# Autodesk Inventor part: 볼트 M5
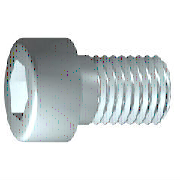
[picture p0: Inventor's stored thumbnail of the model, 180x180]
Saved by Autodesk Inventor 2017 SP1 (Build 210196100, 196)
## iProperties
IsCustomPart: 1
Created: 2012-02
Part Number: 볼트 M5
Material: 강철, 연강
Description: 6각머리 태핑 나사
Document SubType Name: Modeling
Standard: KS B 1003
Designer: mduedu
Standards Organization: KS
Language: ko-KR
Size Designation: M 5 x 16
Categories: <MemberInstance><Categories><Category DisplayName="조임쇠" InternalName="e4da775c-781d-43d5-af7c-5136215cf5a6" Mnemonic="FSTN"><Category DisplayName="볼트" InternalN
Density: 1 g/cm^3
Appearance: 강철
Author: mduedu
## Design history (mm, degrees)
sketch "스케치1"
  geometry: L1 (-1.167, 0)-(16, 0); L2 (16, 0)-(16, 2.5); L3 (16, 2.5)-(2, 2.5); L4 (2, 2.5)-(1.509, 2.5); L5 (1.509, 2.5)-(0, 2.5); L6 (0, 2.5)-(0, 4.25); L7 (0, 4.25)-(-5, 4.25); L8 (-5, 4.25)-(-5, 2.309); L9 (-5, 2.309)-(-2.5, 2.309); L10 (-2.5, 2.309)-(-1.167, 0); L11 (-9.2, 0)-(20.2, 0) reference; L12 (0, -0.85)-(0, 5.1) reference; L13 (2, 2.5)-(0, 2.5)
  constraints: 22 end point, 6 parallel, 2 collinear, 2 perpendicular, 1 horizontal, 1 point on line
  dimensions: "d1" = 14 distance from line of L3.end L2 (= GEL); "d2" = 0.49086 distance of L4.end L3.end (computed from GAL); "d3" = 5 distance between parallel lines of L8 L6 (= KOH); "d4" = 2.5 distance of L8.end L9.end (= INTI); "d5" = 60 deg angle of L10 L1; "d6" = 5 diameter of L3 L1 (= GD); "d7" = 5 diameter of L5 L1 (= BDM); "d8" = 4.6188 diameter of L9 L1 (= 1.1547 x SW); "d9" = 8.5 diameter of L7 L1 (= KOD); "d26" = 16 distance between parallel lines of L12 L2 (= NLG)
revolve "본체" sketch "스케치1" stored, may be unused: angle "d10" = 90 deg
sketch "스케치2"
  geometry: L1 (0, -5.95)-(0, 5.95) reference; L2 (-5.95, 0)-(5.95, 0) reference; L3 (2.309, 0)-(1.155, -2); L4 (1.155, -2)-(-1.155, -2); L5 (-1.155, -2)-(-2.309, 0); L6 (-2.309, 0)-(-1.155, 2); L7 (-1.155, 2)-(1.155, 2); L8 (1.155, 2)-(2.309, 0); 2 further points
  constraints: 12 end point, 1 coincident, 1 horizontal alignment, 1 point on line, 12 other
extrude "슬롯" join sketch "스케치2" stored distance "d11" = 10; taper "d12" = 0 deg
workplane "Work Plane1"
fillet "Fillet2" dims "d30" = 0.1 (= R)
body "Solid1"
fillet "모깎기1" dims "d17" = 0.5 (= RR)
feature "스레드" dims "d13" = 14 (= GEL), "d14" = 0
chamfer "모따기1" distance "d15" = 0.49076 (= -0.5 x SPD + 0.5 x GD); stored, may be unused: second distance "d16" = 0.49076 (= GUL), angle "d27" = 45 deg
other parameters: "GD" = 5 (= NND) [user parameter; used in 2 equation terms], "NLG" = 16 [user parameter; used in 1 equation term], "GEL" = 14 [user parameter; used in 2 equation terms], "KOD" = 8.5 [user parameter; used in 1 equation term], "KOH" = 5 [user parameter; used in 1 equation term], "INTI" = 2.5 [user parameter; used in 1 equation term], "GAL" = 0.49076 (= 0.61345 x PTC) [user parameter; used in 1 equation term], "GUL" = 0.49076 (= 0.61345 x PTC) [user parameter; used in 1 equation term], "BDM" = 5 (= NND) [user parameter; used in 1 equation term], "SW" = 4 [user parameter; used in 2 equation terms], "RR" = 0.5 [user parameter; used in 1 equation term], "SPD" = 4.01848 (= NND - 1.2269 x PTC) [user parameter; used in 1 equation term], "d19" = 0, "d28" = 0, "d29" = 0, "R" = 0.1 [user parameter; used in 1 equation term], "PHH" = 0.2 [user parameter], "GD1" = 4.01848 (= THREADDIA - 1.2269 x PTC) [user parameter], "THREADDIA" = 5 [user parameter; used in 1 equation term], "FAWI" = 45 deg [user parameter], "TPU" = 12.5 (computed from PTC) [user parameter], "PTC" = 0.8 [user parameter; used in 5 equation terms], "NND" = 5 [user parameter; used in 3 equation terms], "TOA" = 30 deg [user parameter], "E0" = 4.62 (= 1.155 x SW) [user parameter]
